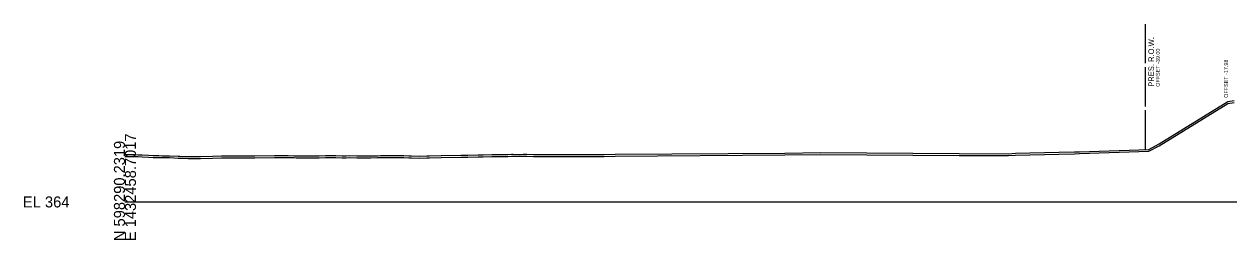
# Model space of a CAD drawing. Extents: x -26 to 2203, y -10 to 12201.
# Drawn here: x -25.7 to 281.3, y 3490.3 to 3545.4 of the extents above; entities that cross this region are included whole.
import ezdxf

# ---------------------------------------------------------------- set-up
doc = ezdxf.new("R2010")
doc.units = 0
for name, color, linetype in [('DESIGN - SHEET - Light Grid', 7, 'Continuous'), ('DESIGN - TYPICAL - Slope Tie Text', 7, 'Continuous'), ('SURVEY - GROUND - Bottom of Topsoil Layer', 7, 'Continuous'), ('SURVEY - GROUND - Top of Ground', 7, 'Continuous'), ('SURVEY - PROPERTY - ROW Lines', 7, 'Continuous'), ('SURVEY - PROPERTY - ROW Lines Text', 7, 'Continuous')]:
    doc.layers.add(name, color=color, linetype=linetype)

msp = doc.modelspace()

# ---------------------------------------------------------------- linework, layer by layer
at = {"layer": 'DESIGN - SHEET - Light Grid'}
msp.add_line((0, 3500), (300, 3500), dxfattribs=at)
at = {"layer": 'SURVEY - GROUND - Bottom of Topsoil Layer'}
for p, q in [((263.46, 3514.36), (280.94, 3525.16)), ((280.94, 3525.16), (282.56, 3525.41)), ((0, 3511.63), (0.72, 3511.64)), ((0.72, 3511.64), (2.41, 3511.58)), ((2.41, 3511.58), (3.37, 3511.56)), ((3.37, 3511.56), (4.37, 3511.5)), ((4.37, 3511.5), (6.02, 3511.43)), ((87.39, 3511.46), (90.02, 3511.49)), ((90.02, 3511.49), (90.84, 3511.51)), ((90.84, 3511.51), (91.29, 3511.53)), ((91.29, 3511.53), (93.49, 3511.58)), ((93.49, 3511.58), (94.55, 3511.63)), ((94.55, 3511.63), (96.14, 3511.62)), ((96.14, 3511.62), (96.51, 3511.63)), ((96.51, 3511.63), (97.54, 3511.64)), ((97.54, 3511.64), (98.47, 3511.66)), ((98.47, 3511.66), (98.8, 3511.66)), ((98.8, 3511.66), (100.43, 3511.65)), ((100.43, 3511.65), (101.45, 3511.68)), ((101.45, 3511.68), (102.39, 3511.66)), ((102.39, 3511.66), (104.1, 3511.62)), ((104.1, 3511.62), (105.07, 3511.62)), ((105.07, 3511.62), (106.31, 3511.6)), ((106.31, 3511.6), (106.75, 3511.6)), ((106.75, 3511.6), (108.27, 3511.62)), ((108.27, 3511.62), (109.4, 3511.63)), ((109.4, 3511.63), (110.23, 3511.64)), ((110.23, 3511.64), (112.05, 3511.6)), ((112.05, 3511.6), (112.6, 3511.59)), ((112.6, 3511.59), (114.15, 3511.57)), ((114.15, 3511.57), (114.7, 3511.57)), ((114.7, 3511.57), (116.11, 3511.62)), ((116.11, 3511.62), (117.35, 3511.63)), ((117.35, 3511.63), (117.83, 3511.63)), ((117.83, 3511.63), (122.06, 3511.64)), ((122.06, 3511.64), (124.93, 3511.68)), ((124.93, 3511.68), (168.1, 3511.99)), ((168.1, 3511.99), (177.2, 3512.13)), ((177.2, 3512.13), (212.57, 3511.87)), ((212.57, 3511.87), (225.09, 3511.82)), ((225.09, 3511.82), (226.9, 3511.97)), ((226.9, 3511.97), (237.9, 3512.19)), ((237.9, 3512.19), (241.94, 3512.31)), ((241.94, 3512.31), (243.22, 3512.33)), ((243.22, 3512.33), (260.85, 3512.92)), ((260.85, 3512.92), (263.46, 3514.36)), ((6.02, 3511.43), (7.22, 3511.37)), ((7.22, 3511.37), (8.3, 3511.33)), ((8.3, 3511.33), (8.67, 3511.32)), ((8.67, 3511.32), (9.46, 3511.31)), ((9.46, 3511.31), (11.32, 3511.31)), ((11.32, 3511.31), (13.55, 3511.18)), ((13.55, 3511.18), (13.97, 3511.17)), ((13.97, 3511.17), (14.75, 3511.14)), ((14.75, 3511.14), (16.14, 3511.12)), ((16.14, 3511.12), (16.62, 3511.09)), ((16.62, 3511.09), (17.64, 3511.09)), ((17.64, 3511.09), (19.28, 3511.11)), ((19.28, 3511.11), (22.28, 3511.21)), ((22.28, 3511.21), (24.58, 3511.27)), ((24.58, 3511.27), (29.8, 3511.27)), ((29.8, 3511.27), (31.82, 3511.26)), ((31.82, 3511.26), (32.12, 3511.25)), ((32.12, 3511.25), (32.53, 3511.26)), ((32.53, 3511.26), (33.11, 3511.27)), ((33.11, 3511.27), (38.1, 3511.33)), ((38.1, 3511.33), (40.48, 3511.37)), ((40.48, 3511.37), (41.62, 3511.33)), ((41.62, 3511.33), (43.13, 3511.31)), ((43.13, 3511.31), (43.58, 3511.3)), ((43.58, 3511.3), (44.86, 3511.27)), ((44.86, 3511.27), (45.78, 3511.25)), ((45.78, 3511.25), (47.5, 3511.27)), ((47.5, 3511.27), (48.43, 3511.25)), ((48.43, 3511.25), (49.46, 3511.29)), ((49.46, 3511.29), (51.08, 3511.34)), ((51.08, 3511.34), (51.42, 3511.34)), ((51.42, 3511.34), (52.38, 3511.35)), ((52.38, 3511.35), (53.38, 3511.36)), ((53.38, 3511.36), (53.73, 3511.37)), ((53.73, 3511.37), (55.34, 3511.29)), ((55.34, 3511.29), (56.38, 3511.28)), ((56.38, 3511.28), (57.3, 3511.32)), ((57.3, 3511.32), (59.04, 3511.28)), ((59.04, 3511.28), (59.91, 3511.28)), ((59.91, 3511.28), (61.69, 3511.29)), ((61.69, 3511.29), (62.65, 3511.3)), ((62.65, 3511.3), (64.34, 3511.31)), ((64.34, 3511.31), (65.14, 3511.33)), ((65.14, 3511.33), (67.1, 3511.33)), ((67.1, 3511.33), (67.44, 3511.33)), ((67.44, 3511.33), (69.06, 3511.35)), ((69.06, 3511.35), (69.64, 3511.35)), ((69.64, 3511.35), (71.02, 3511.32)), ((71.02, 3511.32), (72.29, 3511.29)), ((72.29, 3511.29), (72.99, 3511.26)), ((72.99, 3511.26), (74.96, 3511.21)), ((74.96, 3511.21), (76.91, 3511.27)), ((76.91, 3511.27), (77.59, 3511.28)), ((77.59, 3511.28), (80.53, 3511.34)), ((80.53, 3511.34), (85.54, 3511.44)), ((85.54, 3511.44), (86.71, 3511.45)), ((86.71, 3511.45), (87.39, 3511.46))]:
    msp.add_line(p, q, dxfattribs=at)
at = {"layer": 'SURVEY - GROUND - Top of Ground'}
for p, q in [((263.46, 3514.86), (280.94, 3525.66)), ((280.94, 3525.66), (282.56, 3525.91)), ((260.85, 3513.42), (263.46, 3514.86)), ((0, 3512.13), (0.72, 3512.14)), ((0.72, 3512.14), (2.41, 3512.08)), ((2.41, 3512.08), (3.37, 3512.06)), ((3.37, 3512.06), (4.37, 3512)), ((4.37, 3512), (6.02, 3511.93)), ((6.02, 3511.93), (7.22, 3511.87)), ((7.22, 3511.87), (8.3, 3511.83)), ((8.3, 3511.83), (8.67, 3511.82)), ((8.67, 3511.82), (9.46, 3511.81)), ((9.46, 3511.81), (11.32, 3511.81)), ((11.32, 3511.81), (13.55, 3511.68)), ((13.55, 3511.68), (13.97, 3511.67)), ((13.97, 3511.67), (14.75, 3511.64)), ((14.75, 3511.64), (16.14, 3511.62)), ((16.14, 3511.62), (16.62, 3511.59)), ((16.62, 3511.59), (17.64, 3511.59)), ((17.64, 3511.59), (19.28, 3511.61)), ((19.28, 3511.61), (22.28, 3511.71)), ((22.28, 3511.71), (24.58, 3511.77)), ((24.58, 3511.77), (29.8, 3511.77)), ((29.8, 3511.77), (31.82, 3511.76)), ((31.82, 3511.76), (32.12, 3511.75)), ((32.12, 3511.75), (32.53, 3511.76)), ((32.53, 3511.76), (33.11, 3511.77)), ((33.11, 3511.77), (38.1, 3511.83)), ((38.1, 3511.83), (40.48, 3511.87)), ((40.48, 3511.87), (41.62, 3511.83)), ((41.62, 3511.83), (43.13, 3511.81)), ((43.13, 3511.81), (43.58, 3511.8)), ((43.58, 3511.8), (44.86, 3511.77)), ((44.86, 3511.77), (45.78, 3511.75)), ((45.78, 3511.75), (47.5, 3511.77)), ((47.5, 3511.77), (48.43, 3511.75)), ((48.43, 3511.75), (49.46, 3511.79)), ((49.46, 3511.79), (51.08, 3511.84)), ((51.08, 3511.84), (51.42, 3511.84)), ((51.42, 3511.84), (52.38, 3511.85)), ((52.38, 3511.85), (53.38, 3511.86)), ((53.38, 3511.86), (53.73, 3511.87)), ((53.73, 3511.87), (55.34, 3511.79)), ((55.34, 3511.79), (56.38, 3511.78)), ((56.38, 3511.78), (57.3, 3511.82)), ((57.3, 3511.82), (59.04, 3511.78)), ((59.04, 3511.78), (59.91, 3511.78)), ((59.91, 3511.78), (61.69, 3511.79)), ((61.69, 3511.79), (62.65, 3511.8)), ((62.65, 3511.8), (64.34, 3511.81)), ((64.34, 3511.81), (65.14, 3511.83)), ((65.14, 3511.83), (67.1, 3511.83)), ((67.1, 3511.83), (67.44, 3511.83)), ((67.44, 3511.83), (69.06, 3511.85)), ((69.06, 3511.85), (69.64, 3511.85)), ((69.64, 3511.85), (71.02, 3511.82)), ((71.02, 3511.82), (72.29, 3511.79)), ((72.29, 3511.79), (72.99, 3511.76)), ((72.99, 3511.76), (74.96, 3511.71)), ((74.96, 3511.71), (76.91, 3511.77)), ((76.91, 3511.77), (77.59, 3511.78)), ((77.59, 3511.78), (80.53, 3511.84)), ((80.53, 3511.84), (85.54, 3511.94)), ((85.54, 3511.94), (86.71, 3511.95)), ((86.71, 3511.95), (87.39, 3511.96)), ((87.39, 3511.96), (90.02, 3511.99)), ((90.02, 3511.99), (90.84, 3512.01)), ((90.84, 3512.01), (91.29, 3512.03)), ((91.29, 3512.03), (93.49, 3512.08)), ((93.49, 3512.08), (94.55, 3512.13)), ((94.55, 3512.13), (96.14, 3512.12)), ((96.14, 3512.12), (96.51, 3512.13)), ((96.51, 3512.13), (97.54, 3512.14)), ((97.54, 3512.14), (98.47, 3512.16)), ((98.47, 3512.16), (98.8, 3512.16)), ((98.8, 3512.16), (100.43, 3512.15)), ((100.43, 3512.15), (101.45, 3512.18)), ((101.45, 3512.18), (102.39, 3512.16)), ((102.39, 3512.16), (104.1, 3512.12)), ((104.1, 3512.12), (105.07, 3512.12)), ((105.07, 3512.12), (106.31, 3512.1)), ((106.31, 3512.1), (106.75, 3512.1)), ((106.75, 3512.1), (108.27, 3512.12)), ((108.27, 3512.12), (109.4, 3512.13)), ((109.4, 3512.13), (110.23, 3512.14)), ((110.23, 3512.14), (112.05, 3512.1)), ((112.05, 3512.1), (112.6, 3512.09)), ((112.6, 3512.09), (114.15, 3512.07)), ((114.15, 3512.07), (114.7, 3512.07)), ((114.7, 3512.07), (116.11, 3512.12)), ((116.11, 3512.12), (117.35, 3512.13)), ((117.35, 3512.13), (117.83, 3512.13)), ((117.83, 3512.13), (122.06, 3512.14)), ((122.06, 3512.14), (124.93, 3512.18)), ((124.93, 3512.18), (168.1, 3512.49)), ((168.1, 3512.49), (177.2, 3512.63)), ((177.2, 3512.63), (212.57, 3512.37)), ((212.57, 3512.37), (225.09, 3512.32)), ((225.09, 3512.32), (226.9, 3512.47)), ((226.9, 3512.47), (237.9, 3512.69)), ((237.9, 3512.69), (241.94, 3512.81)), ((241.94, 3512.81), (243.22, 3512.83)), ((243.22, 3512.83), (260.85, 3513.42))]:
    msp.add_line(p, q, dxfattribs=at)
at = {"layer": 'SURVEY - PROPERTY - ROW Lines'}
for p, q in [((260, 3535.39), (260, 3545.39)), ((260, 3524.39), (260, 3534.39)), ((260, 3513.39), (260, 3523.39))]:
    msp.add_line(p, q, dxfattribs=at)

# ---------------------------------------------------------------- texts
at = {"layer": 'DESIGN - SHEET - Light Grid'}
for s, p in [('N 598290.2319', (0, 3490)), ('E 1432458.7017', (2.8, 3490))]:
    msp.add_text(s, height=2.8, rotation=90, dxfattribs=at).set_placement(p)
msp.add_text('EL 364', height=2.8, dxfattribs=at).set_placement((-26, 3498.6))
at = {"layer": 'DESIGN - TYPICAL - Slope Tie Text'}
msp.add_text('OFFSET -17.98', height=1, rotation=90, dxfattribs=at).set_placement((281.02, 3526.58))
at = {"layer": 'SURVEY - PROPERTY - ROW Lines Text'}
for s, height, p in [('PRES. R.O.W.', 1.4, (262.15, 3529.39)), ('OFFSET -39.00', 1, (263.65, 3529.39))]:
    msp.add_text(s, height=height, rotation=90, dxfattribs=at).set_placement(p)

doc.saveas('drawing.dxf')
